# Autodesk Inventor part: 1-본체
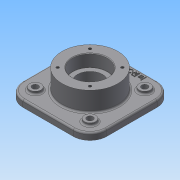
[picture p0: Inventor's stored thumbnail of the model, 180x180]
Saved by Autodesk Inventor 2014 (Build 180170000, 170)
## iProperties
Created: 2015-09
Part Number: 1-본체
Material: Generic
Document SubType Name: Modeling
Designer: study
Density: 1 g/cm^3
Appearance: Default
Author: study
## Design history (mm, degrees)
sketch "스케치1"
  geometry: L1 (75, -75)-(-75, -75); L2 (-75, -75)-(-75, 75); L3 (-75, 75)-(75, 75); L4 (75, 75)-(75, -75); 2 further points
  constraints: 8 end point, 1 coincident, 1 vertical, 9 other
  dimensions: "d0" = 150 distance of L2.end L3.end
extrude "돌출1" new body sketch "스케치1" distance "d1" = 12; taper "d2" = 0 deg
node "작업 평면1"
sketch "스케치2"
  geometry: C1 r 50 at (0, 0); 1 further point
  constraints: 1 centre point, 1 coincident
  dimensions: "d4" = 100 diameter of C1
extrude "돌출2" join sketch "스케치2" distance "d5" = 70; taper "d6" = 0 deg
sketch "스케치3"
  geometry: L1 (-49, 49)-(49, 49); L2 (49, 49)-(49, -49); L3 (49, -49)-(-49, -49); L4 (-49, -49)-(-49, 49); L5 (-49, 49)-(49, -49); L6 (49, 49)-(-49, -49); C1 r 50 at (0, 0) reference; C2 r 10 at (-49, 49); C3 r 10 at (49, 49); C4 r 10 at (49, -49); C5 r 10 at (-49, -49)
  constraints: 12 end point, 4 centre point, 4 coincident, 3 equal radius, 2 midpoint, 2 parallel, 1 horizontal, 1 perpendicular
  dimensions: "d7" = 98 distance of L1.start L1.end; "d8" = 98 distance of L3.end L1.start; "d9" = 20 diameter of C2
extrude "돌출3" join sketch "스케치3" distance "d10" = 5; taper "d11" = 0 deg
hole "구멍1" diameter "d14" = 45; stored, may be unused: countersink angle "d18" = 90 deg, drill point angle "d20" = 0 deg; dims "d12" = 10, "d13" = 10, "d15" = 6, "d16" = 62, "d17" = 22, "d19" = 8
hole "구멍2" diameter "d23" = 45; stored, may be unused: countersink angle "d27" = 90 deg, drill point angle "d29" = 0 deg; dims "d21" = 10, "d22" = 10, "d24" = 6, "d25" = 62, "d26" = 22, "d28" = 8
sketch "스케치4"
  geometry: L1 (0, 0)-(-41, 0); L2 (0, 0)-(-28.991, 28.991); C1 r 50 at (0, 0) reference; A1 r 41 centre (0, 0) between (-41, 0) and (-28.991, 28.991); 1 further point
  constraints: 4 end point, 2 coincident, 2 point on circle, 1 centre point, 1 horizontal
  dimensions: "d30" = 82 diameter of A1; "d32" = 45 deg angle of L1 L2
hole "구멍3" sketch "스케치4" at (-28.991, 28.991) diameter "d33" = 4.917; stored, may be unused: countersink angle "d37" = 90 deg, drill point angle "d39" = 118 deg; dims "d34" = 10, "d35" = 62, "d36" = 22, "d38" = 13
node "작업 평면2"
hole "구멍4" diameter "d45" = 11; stored, may be unused: countersink angle "d49" = 90 deg, drill point angle "d51" = 118 deg; dims "d43" = 10, "d44" = 10, "d46" = 10, "d47" = 62, "d48" = 22, "d50" = 13
hole "구멍5" diameter "d54" = 11; stored, may be unused: countersink angle "d58" = 90 deg, drill point angle "d60" = 118 deg; dims "d52" = 10, "d53" = 10, "d55" = 10, "d56" = 62, "d57" = 22, "d59" = 13
hole "구멍6" diameter "d63" = 11; stored, may be unused: countersink angle "d67" = 90 deg, drill point angle "d69" = 118 deg; dims "d61" = 10, "d62" = 10, "d64" = 10, "d65" = 62, "d66" = 22, "d68" = 13
hole "구멍7" diameter "d72" = 11; stored, may be unused: countersink angle "d76" = 90 deg, drill point angle "d78" = 118 deg; dims "d70" = 10, "d71" = 10, "d73" = 10, "d74" = 62, "d75" = 22, "d77" = 13
sketch "스케치5"
  geometry: C1 r 50 at (0, 0) reference; 1 further point
  constraints: 1 vertical alignment, 1 other
  dimensions: "d79" = 65 distance of point (0, 65) C1.centre
feature "엠보싱1" sketch "스케치5" dims "d0" = 150, "d9" = 20, "d80" = 1, "d81" = 0
chamfer "모따기1" distance "d82" = 1; stored, may be unused: second distance "d83" = 2, angle "d84" = 45 deg
fillet "모깎기1" dims "d85" = 0.3, "d86" = 30
fillet "모깎기2" dims "d87" = 3
node "솔리드1"
pattern_circular "원형 패턴1" dims angle "d41" = 360 deg
mirror "대칭1"
other parameters: "d3" = 23
